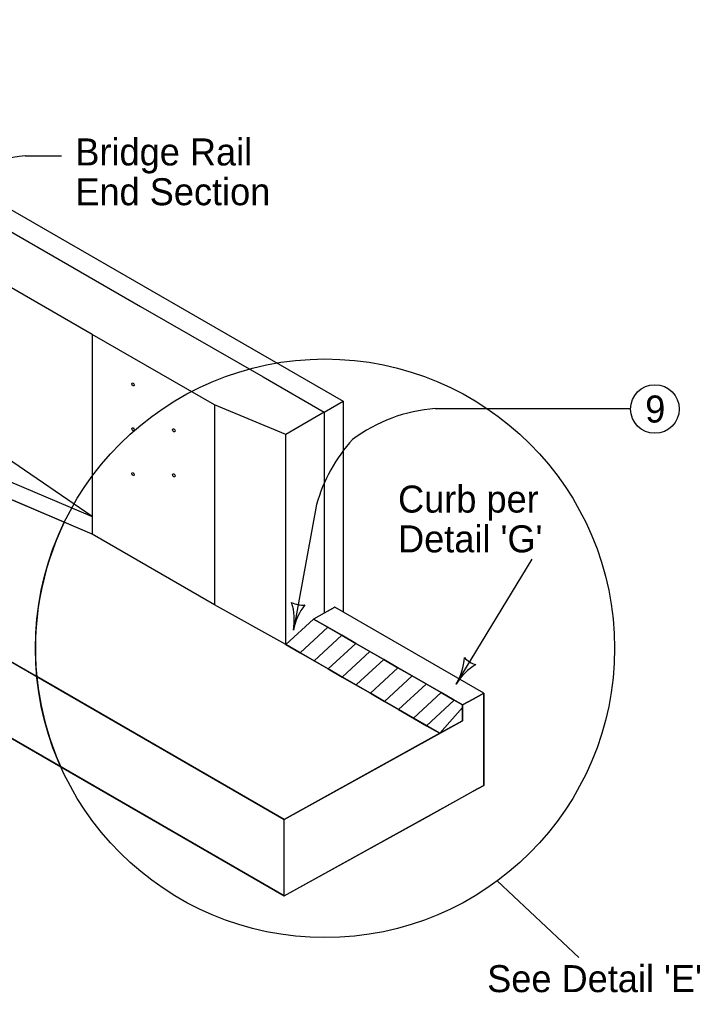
# Model space of a CAD drawing. Extents: x -2135039 to -2120895, y -2139150 to -2136566.
# Drawn here: x -2122188 to -2121695, y -2137838 to -2137117 of the extents above; entities that cross this region are included whole.
import ezdxf

# ---------------------------------------------------------------- set-up
doc = ezdxf.new("R2010")
doc.units = 0
for name, color, linetype in [('dsnStdLabel', 7, 'Continuous'), ('Level 1', 7, 'Continuous'), ('Level 2', 7, 'Continuous')]:
    doc.layers.add(name, color=color, linetype=linetype)

msp = doc.modelspace()

# ---------------------------------------------------------------- linework, layer by layer
at = {"layer": 'dsnStdLabel'}
for centre, radius, start, end in [((-2121978.73, -2137534.54), 16.42, 241.78197, 277.24867), ((-2122027.01, -2137561.85), 42.5, 349.51532, 17.58781), ((-2121943.42, -2137577.32), 42.5, 141.44283, 169.51532), ((-2121901.16, -2137587.38), 42.5, 328.71083, 356.78332), ((-2121846.33, -2137579), 16.42, 220.97747, 256.44418), ((-2121828.52, -2137631.52), 42.5, 120.63834, 148.71083)]:
    msp.add_arc(centre, radius, start, end, dxfattribs=at)
at = {"layer": 'Level 2'}
for p, q in [((-2122450.03, -2137110.37), (-2121948.26, -2137400.06)), ((-2122183.62, -2137218.46), (-2122156.75, -2137218.46)), ((-2122133.99, -2137350.53), (-2122133.99, -2137498.41)), ((-2122043.48, -2137402.78), (-2122043.48, -2137550.67)), ((-2121962.4, -2137408.23), (-2121948.26, -2137400.06)), ((-2121948.26, -2137400.06), (-2121948.26, -2137556.22)), ((-2122154.63, -2137489.65), (-2122343.3, -2137409.58)), ((-2122133.99, -2137498.41), (-2122343.3, -2137409.58)), ((-2121880.23, -2137405.46), (-2121735.81, -2137405.46)), ((-2121990.69, -2137580.24), (-2121990.69, -2137424.56)), ((-2122175.01, -2137603.92), (-2122429.17, -2137457.18)), ((-2122429.17, -2137457.18), (-2122175.01, -2137603.92)), ((-2122429.17, -2137457.18), (-2121991.9, -2137709.64)), ((-2121968, -2137476.58), (-2121985.22, -2137569.58)), ((-2122133.99, -2137498.41), (-2122154.63, -2137489.65)), ((-2122043.48, -2137550.67), (-2122133.99, -2137498.41)), ((-2122043.48, -2137550.67), (-2122133.99, -2137498.41)), ((-2122429.17, -2137513.79), (-2121991.9, -2137766.25)), ((-2122429.17, -2137513.79), (-2122157.21, -2137670.81)), ((-2121991.9, -2137766.25), (-2122429.17, -2137513.79)), ((-2121864.84, -2137609.45), (-2121808.7, -2137517.07)), ((-2121990.69, -2137580.24), (-2122043.48, -2137550.67)), ((-2121990.69, -2137580.24), (-2122043.48, -2137550.67)), ((-2121844.35, -2137616.21), (-2121954.55, -2137552.59)), ((-2121844.35, -2137616.21), (-2121954.55, -2137552.59)), ((-2121970.26, -2137561.29), (-2121990.69, -2137580.24)), ((-2121970.26, -2137561.29), (-2121990.69, -2137580.24)), ((-2121962.4, -2137556.94), (-2121970.26, -2137561.29)), ((-2121959.82, -2137567.32), (-2121970.26, -2137561.29)), ((-2121970.26, -2137561.29), (-2121959.82, -2137567.32)), ((-2121860.06, -2137624.91), (-2121970.26, -2137561.29)), ((-2121980.26, -2137586.26), (-2121959.82, -2137567.32)), ((-2121959.82, -2137567.32), (-2121980.26, -2137586.26)), ((-2121959.82, -2137567.32), (-2121980.26, -2137586.26)), ((-2121949.42, -2137573.32), (-2121959.82, -2137567.32)), ((-2121959.82, -2137567.32), (-2121949.42, -2137573.32)), ((-2121969.85, -2137592.27), (-2121949.42, -2137573.32)), ((-2121949.42, -2137573.32), (-2121969.85, -2137592.27)), ((-2121949.42, -2137573.32), (-2121969.85, -2137592.27)), ((-2121939.02, -2137579.33), (-2121949.42, -2137573.32)), ((-2121949.42, -2137573.32), (-2121939.02, -2137579.33)), ((-2121980.26, -2137586.26), (-2121990.69, -2137580.24)), ((-2121990.69, -2137580.24), (-2121980.26, -2137586.26)), ((-2121876.93, -2137645.92), (-2121990.69, -2137580.24)), ((-2121959.45, -2137598.27), (-2121939.02, -2137579.33)), ((-2121939.02, -2137579.33), (-2121959.45, -2137598.27)), ((-2121939.02, -2137579.33), (-2121959.45, -2137598.27)), ((-2121928.62, -2137585.33), (-2121939.02, -2137579.33)), ((-2121939.02, -2137579.33), (-2121928.62, -2137585.33)), ((-2121980.26, -2137586.26), (-2121969.85, -2137592.27)), ((-2121949.05, -2137604.28), (-2121928.62, -2137585.33)), ((-2121928.62, -2137585.33), (-2121949.05, -2137604.28)), ((-2121928.62, -2137585.33), (-2121949.05, -2137604.28)), ((-2121918.35, -2137591.26), (-2121938.43, -2137609.88)), ((-2121969.85, -2137592.27), (-2121959.45, -2137598.27)), ((-2121959.45, -2137598.27), (-2121949.05, -2137604.28)), ((-2121928.25, -2137616.29), (-2121907.82, -2137597.34)), ((-2121907.82, -2137597.34), (-2121928.25, -2137616.29)), ((-2121907.82, -2137597.34), (-2121928.25, -2137616.29)), ((-2121897.41, -2137603.35), (-2121907.82, -2137597.34)), ((-2121907.82, -2137597.34), (-2121897.41, -2137603.35)), ((-2122175.01, -2137603.92), (-2121991.9, -2137709.64)), ((-2121991.9, -2137709.64), (-2122175.01, -2137603.92)), ((-2121949.05, -2137604.28), (-2121928.25, -2137616.29)), ((-2121917.85, -2137622.29), (-2121897.41, -2137603.35)), ((-2121897.41, -2137603.35), (-2121917.85, -2137622.29)), ((-2121897.41, -2137603.35), (-2121917.85, -2137622.29)), ((-2121886.9, -2137609.42), (-2121907.34, -2137628.36)), ((-2121928.25, -2137616.29), (-2121917.85, -2137622.29)), ((-2121875.91, -2137615.74), (-2121896.34, -2137634.68)), ((-2121844.35, -2137616.21), (-2121852.21, -2137620.56)), ((-2121852.21, -2137620.56), (-2121844.35, -2137616.21)), ((-2121844.35, -2137616.21), (-2121852.21, -2137620.56)), ((-2121844.35, -2137684.47), (-2121844.35, -2137616.21)), ((-2121917.85, -2137622.29), (-2121907.34, -2137628.36)), ((-2121886.64, -2137640.31), (-2121866.21, -2137621.36)), ((-2121866.21, -2137621.36), (-2121886.64, -2137640.31)), ((-2121866.21, -2137621.36), (-2121886.64, -2137640.31)), ((-2121876.93, -2137645.92), (-2121860.06, -2137626.82)), ((-2121860.06, -2137626.82), (-2121876.93, -2137645.92)), ((-2121876.93, -2137645.92), (-2121860.06, -2137626.82)), ((-2121860.06, -2137624.91), (-2121866.21, -2137621.36)), ((-2121866.21, -2137621.36), (-2121860.06, -2137624.91)), ((-2121852.21, -2137620.56), (-2121860.06, -2137624.91)), ((-2121860.06, -2137624.91), (-2121852.21, -2137620.56)), ((-2121852.21, -2137620.56), (-2121860.06, -2137624.91)), ((-2121860.06, -2137626.82), (-2121860.06, -2137624.91)), ((-2121860.06, -2137636.57), (-2121860.06, -2137624.91)), ((-2121860.06, -2137636.57), (-2121860.06, -2137626.82)), ((-2121907.34, -2137628.36), (-2121886.64, -2137640.31)), ((-2121991.9, -2137709.64), (-2121860.06, -2137636.57)), ((-2121886.64, -2137640.31), (-2121880.49, -2137643.86)), ((-2121860.06, -2137636.57), (-2121876.93, -2137645.92)), ((-2121876.93, -2137645.92), (-2121860.06, -2137636.57)), ((-2121991.9, -2137709.64), (-2121876.93, -2137645.92)), ((-2121876.93, -2137645.92), (-2121991.9, -2137709.64)), ((-2121876.93, -2137645.92), (-2121880.49, -2137643.86)), ((-2121880.49, -2137643.86), (-2121876.93, -2137645.92)), ((-2122157.21, -2137670.81), (-2121991.9, -2137766.25)), ((-2121852.21, -2137688.82), (-2121844.35, -2137684.47)), ((-2121844.35, -2137684.47), (-2121852.21, -2137688.82)), ((-2121887.47, -2137708.37), (-2121852.21, -2137688.82)), ((-2121867.29, -2137697.18), (-2121852.21, -2137688.82)), ((-2121991.9, -2137766.25), (-2121867.29, -2137697.18)), ((-2121991.9, -2137766.25), (-2121991.9, -2137709.64)), ((-2121834.41, -2137755.19), (-2121774.11, -2137811.98))]:
    msp.add_line(p, q, dxfattribs=at)
for points in [[(-2122464.17, -2137118.53), (-2122098.17, -2137329.85), (-2122007.66, -2137382.1), (-2121962.4, -2137408.23), (-2121990.69, -2137424.56), (-2122043.48, -2137402.78), (-2122133.99, -2137350.53), (-2122315.01, -2137246.02), (-2122500, -2137139.22)], [(-2122343.3, -2137396.52), (-2122133.99, -2137485.35), (-2122324.45, -2137355.15)], [(-2121962.4, -2137408.23), (-2121962.4, -2137556.94)], [(-2121954.55, -2137552.59), (-2121955.33, -2137553.02), (-2121962.4, -2137556.94)], [(-2121954.55, -2137552.59), (-2121962.4, -2137556.94)], [(-2121962.4, -2137556.94), (-2121970.26, -2137561.29)], [(-2121959.45, -2137598.27), (-2121969.85, -2137592.27), (-2121980.26, -2137586.26)], [(-2121907.82, -2137597.34), (-2121918.35, -2137591.26), (-2121928.62, -2137585.33)], [(-2121928.62, -2137585.33), (-2121918.35, -2137591.26), (-2121907.82, -2137597.34)], [(-2121928.25, -2137616.29), (-2121949.05, -2137604.28), (-2121959.45, -2137598.27)], [(-2121866.21, -2137621.36), (-2121875.93, -2137615.75), (-2121897.41, -2137603.35)], [(-2121897.41, -2137603.35), (-2121875.93, -2137615.75), (-2121866.21, -2137621.36)], [(-2121880.49, -2137643.86), (-2121886.64, -2137640.31), (-2121907.34, -2137628.36), (-2121917.85, -2137622.29), (-2121928.25, -2137616.29)], [(-2121844.35, -2137616.21), (-2121844.35, -2137684.47)], [(-2121860.06, -2137624.91), (-2121860.06, -2137626.82), (-2121860.06, -2137636.57)], [(-2121991.9, -2137766.25), (-2121887.47, -2137708.37), (-2121867.29, -2137697.18)]]:
    msp.add_lwpolyline(points, dxfattribs=at)
for centre, radius in [((-2121961.82, -2137582.99), 214.21), ((-2121717.82, -2137405.81), 18)]:
    msp.add_circle(centre, radius, dxfattribs=at)
for centre, radius, start, end in [((-2122175.93, -2137309.18), 91.05, 94.84094, 140.14667), ((-2121871.34, -2137522.6), 117.48, 94.33989, 126.62701), ((-2121854.68, -2137507.54), 117.48, 137.59711, 164.71953), ((-2121961.82, -2137582.99), 214.21, 154.16871, 185.60632), ((-2121961.82, -2137582.99), 214.21, 154.16871, 185.60632), ((-2121961.82, -2137582.99), 214.21, 185.60632, 204.20182), ((-2121961.82, -2137582.99), 214.21, 185.60632, 204.20182)]:
    msp.add_arc(centre, radius, start, end, dxfattribs=at)
for centre in [(-2122103.82, -2137387.65), (-2122103.82, -2137420.86), (-2122073.65, -2137421.67), (-2122103.82, -2137454.06), (-2122073.65, -2137454.88)]:
    msp.add_ellipse(centre, major_axis=(0.67, -1.15), ratio=0.57735, dxfattribs=at)

# ---------------------------------------------------------------- texts
at = {"layer": 'Level 1'}
msp.add_text('9', height=20, dxfattribs=at).set_placement((-2121724.96, -2137415.81))
at = {"layer": 'Level 2'}
for s, p in [('Bridge Rail ', (-2122146.48, -2137225.49)), ('End Section', (-2122146.48, -2137254.94)), ('Curb per', (-2121907.78, -2137482.48)), ("Detail 'G'", (-2121907.78, -2137511.94)), ("See Detail 'E'", (-2121841.87, -2137837.55))]:
    msp.add_text(s, height=20, dxfattribs=at).set_placement(p)

doc.saveas('drawing.dxf')
